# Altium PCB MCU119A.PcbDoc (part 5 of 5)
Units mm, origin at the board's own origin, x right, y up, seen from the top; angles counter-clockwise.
Board outline 58.62 x 144.37 mm, 6 copper layers (Top Signal, GND, Middle Signal, PWR, GND2, Bottom Signal), stack 1.566 mm thick; 316 components, 238 nets, 1210 pads, 1064 vias.
Unrouted connection lines stored in the file: 59.
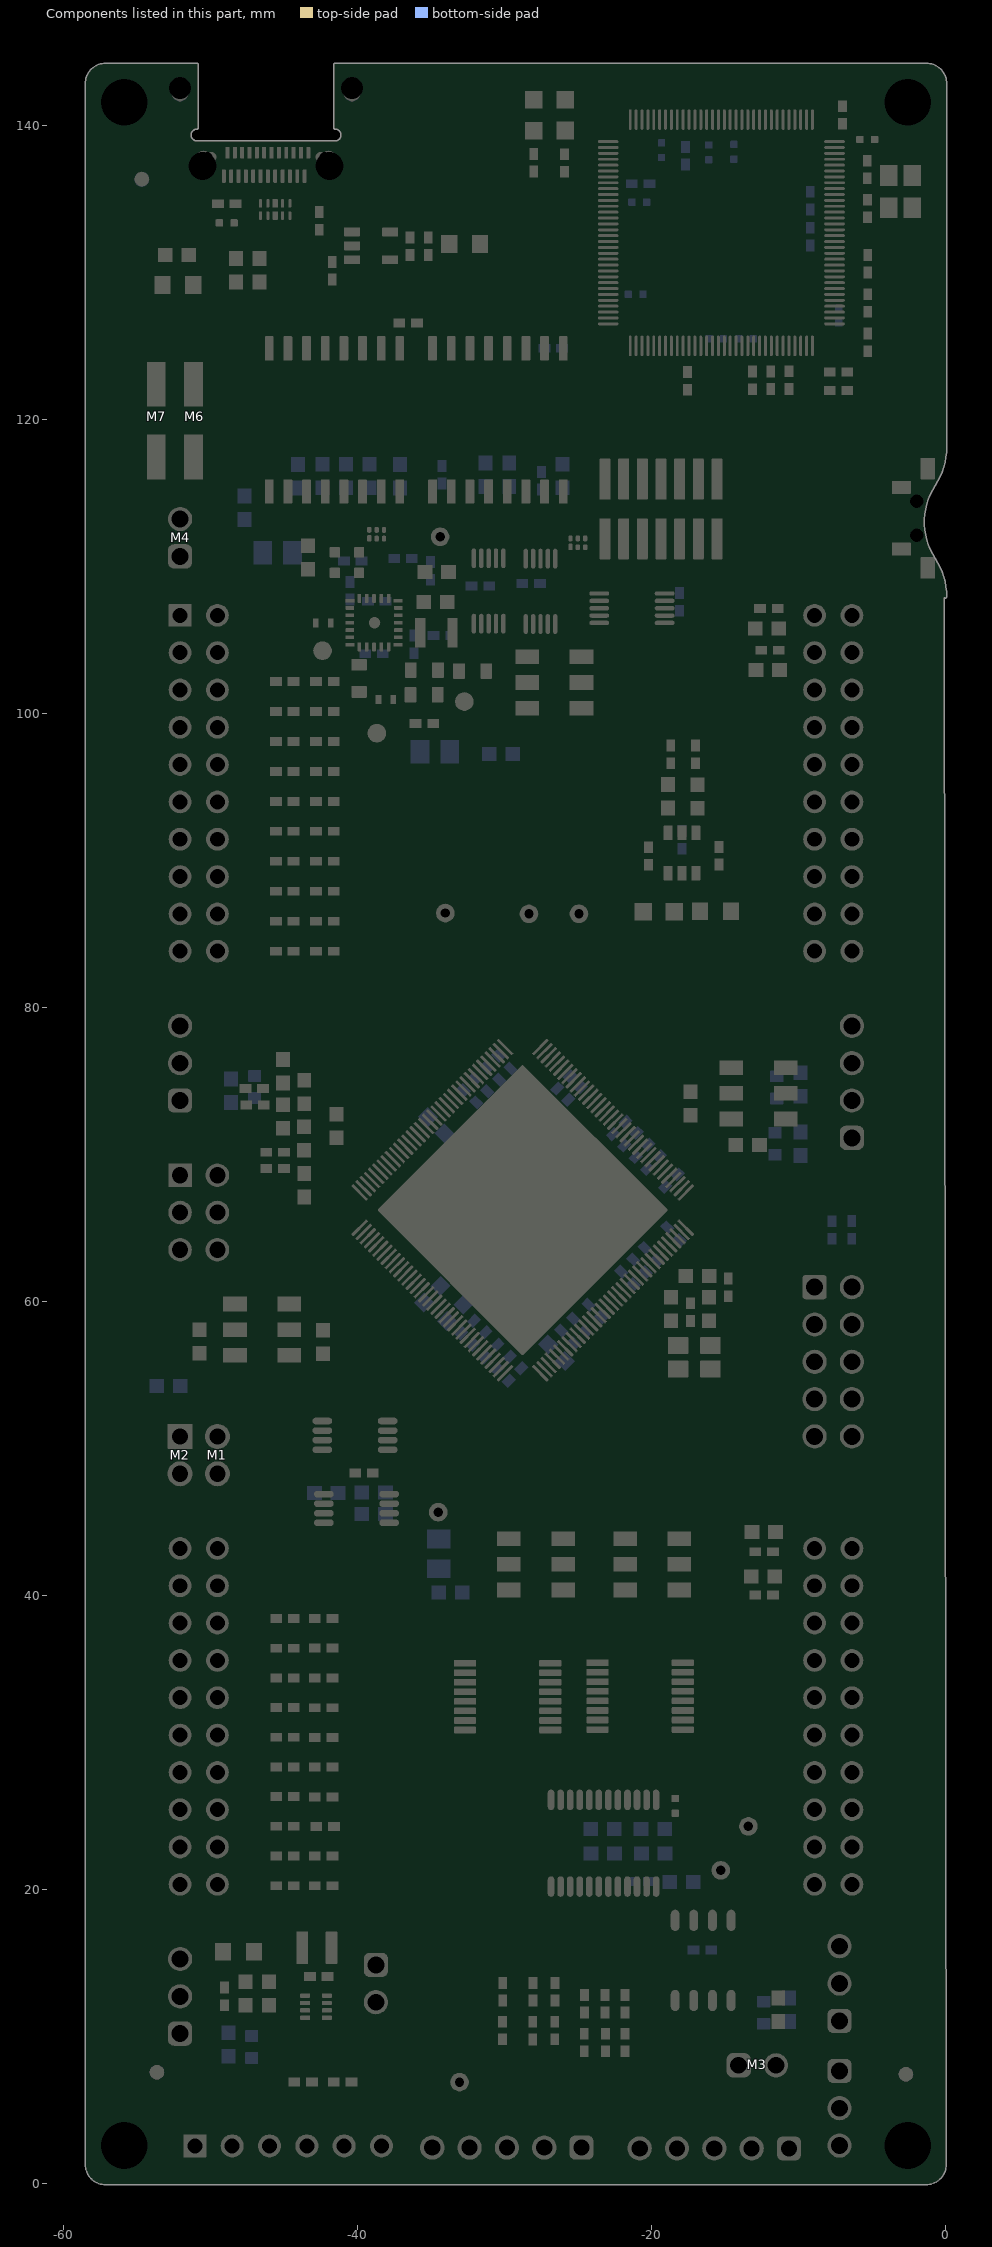
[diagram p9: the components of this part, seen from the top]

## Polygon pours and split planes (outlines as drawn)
+3V3_MCU on PWR "PWR_+3V3_MCU_P156" (solid, remove dead copper, pour order 156): -58.223,118.663 0.057,118.663 0.102,118.618 0.102,-0.1 -57.913,-0.1 -58.42,0.406 -58.42,118.466
VDDIO on PWR "PWR_VDDIO_P151" (solid, remove dead copper, pour order 151): -44.755,106.451 -43.043,106.451 -42.799,106.207 -42.799,102.982 -41.163,101.346 -38.383,101.346 -36.808,99.771 -29.267,99.771 -24.79,95.295 -24.79,83.134 -13.818,72.161 -13.818,58.369 -21.24,50.947 -32.811,50.947 -33.884,52.019 -33.884,55.168 -33.171,55.88 -32.741,55.88 -31.166,54.305 -30.638,54.305 -30.435,54.508 -27.021,54.508 -23.868,57.661 -22.819,57.661 -22.327,58.153 -22.327,59.381 -20.828,60.879 -19.683,60.879 -17.729,62.833 -17.729,67.31 -16.942,68.097 -16.942,68.97 -17.543,69.571 -18.376,69.571 -20.356,71.55 -20.356,72.803 -25.134,77.581 -29.139,77.581 -29.389,77.332 -32.194,77.332 -33.239,76.287 -33.376,76.287 -33.503,76.414 -33.503,78.202 -31.364,80.341 -31.364,91.985 -34.539,95.159 -42.785,95.159 -45.277,97.652 -45.277,105.929
VDD on PWR "PWR_VDD_P152" (solid, remove dead copper, pour order 152): -10.973,72.695 -8.534,72.695 -8.128,72.288 -8.128,68.442 -10.744,65.826 -10.744,53.721 -16.662,47.803 -36.394,47.803 -38.152,49.562 -38.152,56.463 -34.816,59.799 -32.561,57.543 -32.561,56.961 -34.138,55.384 -34.138,51.623 -33.289,50.775 -21.071,50.775 -13.584,58.261 -13.584,70.189 -11.125,72.649
VDDA on PWR "PWR_VDDA_P155" (solid, remove dead copper, pour order 155): -35.907,73.539 -35.708,73.339 -35.708,59.201 -38.456,56.453 -38.456,49.22 -36.734,47.498 -33.654,47.498 -33.306,47.15 -33.306,44.913 -33.795,44.425 -40.066,44.425 -43.84,48.199 -43.84,69.052 -39.354,73.539
+5V0_MCU on PWR "PWR_+5V0_MCU_P149" (solid, remove dead copper, pour order 149): -18.872,21.768 -17.602,20.498 -17.602,18.771 -17.602,1.549 -18.186,0.965 -50.952,0.965 -57.252,7.264 -57.252,117.128 -56.574,117.805 -46.844,117.805 -37.878,108.839 -33.731,108.839 -33.122,108.229 -33.122,101.189 -34.26,100.051 -36.982,100.051 -38.862,101.93 -41.275,101.93 -42.545,103.2 -42.545,106.704 -42.699,106.858 -46.634,106.858 -48.031,105.461 -49.479,105.461 -50.673,106.655 -50.673,107.351 -51.463,108.14 -52.819,108.14 -53.391,107.569 -53.391,75.336 -53.035,74.981 -47.9,74.981 -46.711,73.791 -46.711,70.917 -47.579,70.049 -52.963,70.049 -53.516,69.496 -53.516,57.633 -49.909,54.026 -47.981,52.098 -47.981,28.981 -40.767,21.768 -26.878,21.768
VDD on PWR "PWR_VDD_P150" (solid, remove dead copper, pour order 150): -36.494,94.92 -34.733,94.92 -31.623,91.81 -31.623,80.42 -34.087,77.956 -34.087,76.708 -33.503,76.124 -33.172,76.124 -32.093,77.203 -24.955,77.203 -20.549,72.796 -20.549,71.505 -18.284,69.24 -17.653,69.24 -17.272,68.859 -17.272,68.016 -17.907,67.381 -17.907,62.835 -19.756,60.985 -20.955,60.985 -22.479,59.461 -22.479,58.217 -22.911,57.785 -23.951,57.785 -27.096,54.64 -30.501,54.64 -30.759,54.381 -31.09,54.381 -33.376,56.667 -33.96,56.667 -35.532,58.239 -35.532,62.832 -35.532,73.682 -38.202,76.352 -38.202,93.212
+3V3_XDS110 on PWR "PWR_+3V3_XDS110_P091" (solid, remove dead copper, pour order 91): -4.058,140.669 -1.363,137.974 -1.363,125.196 -1.363,123.197 -3.5,121.06 -43.713,121.06 -45.206,122.553 -45.206,126.708 -37.534,134.381 -28.047,134.381 -21.759,140.669
+5V0_USB on PWR "PWR_+5V0_USB_P096" (solid, remove dead copper, pour order 96): -57.344,122.278 -56.576,121.314 -46.03,121.314 -39.669,132.16 -31.012,132.16 -22.274,140.897 -7.535,140.897 -7.533,140.899 -6.027,140.899 -5.599,141.328 -5.599,143.114 -6.223,143.737 -24,143.737 -29.202,138.535 -44.543,138.535 -55.338,138.535 -57.344,136.529
GND on Top Signal "TOP_SIGNAL_GND_P147" (solid, remove dead copper, pour order 147): -58.223,118.663 0.057,118.663 0.102,118.618 0.102,-0.1 -57.913,-0.1 -58.42,0.406 -58.42,118.466
+3V3_ISO_JTAG on Top Signal "TOP_SIGNAL_+3V3_ISO_JTAG_P114" (solid, remove dead copper, pour order 114): -45.794,118.119 -45.25,118.663 -14.892,118.663 -13.826,117.597 -13.826,113.667 -14.885,112.607 -44.556,112.607 -45.808,113.86
+5V0_MCU on Top Signal "TOP_SIGNAL_+5V0_MCU_P144" (solid, remove dead copper, pour order 144): -55.575,118.663 -53.105,118.663 -52.948,118.505 -52.948,114.016 -51.73,112.798 -48.722,112.798 -47.498,111.574 -47.498,106.223 -48.108,105.613 -50.165,105.613 -50.876,106.324 -50.876,107.4 -51.248,107.772 -57.353,107.772 -57.48,107.899 -57.48,117.14 -55.952,118.669 -55.778,118.669
GND on Top Signal "TOP_SIGNAL_GND_P125" (solid, remove dead copper, pour order 125): -30.822,68.647 -29.662,70.229 -29.649,70.229 -29.457,70.42 -28.513,70.42 -28.513,69.603 -27.534,69.603 -27.534,68.748 -27.635,68.647
+3V3_XDS110 on Top Signal "Top Signal-+3V3_XDS110" (solid, remove dead copper, pour order 100): -23.659,135.528 -23.659,133.176 -23.648,132.748 -20.742,132.748 -20.286,133.204 -20.286,137.677 -22.113,137.677 -22.309,137.481 -22.309,136.726 -23.659,136.726
+5V0_USB on Top Signal "TOP_SIGNAL_+5V0_USB_P101" (solid, remove dead copper, pour order 101): -44.387,133.316 -44.187,133.516 -41.764,133.516 -41.764,134.05 -41.441,134.373 -39.467,134.373 -39.467,132.437 -39.548,132.356 -40.921,132.356 -41.114,132.163 -41.114,131.547 -40.939,131.372 -39.718,131.372 -39.467,131.122 -39.467,130.446 -39.822,130.092 -44.118,130.092 -44.514,130.487
+5V0_USB on Top Signal "TOP_SIGNAL_+5V0_USB_P112" (solid, remove dead copper, pour order 112): -57.941,126.115 -53.045,126.115 -53.045,121.06 -57.941,121.06
USB_GND on Top Signal "TOP_SIGNAL_USB_GND_P122" (solid, remove dead copper, pour order 122): -57.788,143.737 -0.346,143.737 -0.346,121.06 -57.788,121.06
GND on Bottom Signal "BOTTOM_SIGNAL_GND_P143" (solid, remove dead copper, pour order 143): -58.318,118.663 0.057,118.663 0.102,118.618 0.102,-0.1 -57.761,-0.1 -58.42,0.559 -58.42,118.466 -58.293,118.593
USB_GND on Bottom Signal "BOTTOM_SIGNAL_USB_GND_P108" (solid, remove dead copper, pour order 108): -57.773,144.149 -0.346,144.149 -0.346,121.908 -1.337,121.314 -57.131,121.314 -57.773,121.81
GND on GND "GND_GND_P140" (solid, remove dead copper, pour order 140): -58.318,118.663 0.057,118.663 0.102,118.618 0.102,-0.1 -58.42,-0.1 -58.42,118.466 -58.293,118.593
USB_GND on GND "GND_USB_GND_P083" (solid, remove dead copper, pour order 83): -57.788,143.737 -0.346,143.737 -0.346,121.06 -57.788,121.06
GND on GND2 "GND2_GND_P142" (solid, remove dead copper, pour order 142): -58.318,118.663 0.057,118.663 0.102,118.618 0.102,-0.1 -58.42,-0.1 -58.42,118.466 -58.293,118.593
USB_GND on GND2 "GND2_USB_GND_P085" (solid, remove dead copper, pour order 85): -57.877,143.421 -57.15,144.149 -0.346,144.149 -0.346,121.06 -57.877,121.06
GND on Middle Signal "MIDDLE_SIGNAL_GND_P141" (solid, remove dead copper, pour order 141): -58.318,118.663 0.057,118.663 0.102,118.618 0.102,-0.1 -58.42,-0.1 -58.42,118.466 -58.293,118.593

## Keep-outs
Keep-Out Layer:
  lines w0.2: -50.911,144.165 -57.141,144.165 ccw(c-57.141,142.895) -58.411,142.895 -58.411,1.27 ccw(c-57.141,1.27) -57.141,0 -1.27,0 ccw(c-1.27,1.27) 0,1.27 0,107.97 ; -41.511,144.165 -1.261,144.165 cw(c-1.261,142.895) 0.009,142.895 0.009,118.13 cw(c-4.605,118.13) -0.753,115.59 ccw(c3.099,113.05) -0.753,110.51 cw(c-4.605,107.97) 0.009,107.97
  text ".Layer_Name" at -46.609,-58.823 h1.52

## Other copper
Top Signal:
  region net +3V3_MCU: -35.798,110.114 -35.128,109.444 -35.128,109.169 -36.711,107.586 -37.451,107.586 -37.499,107.634 -37.499,109.113 -36.499,110.114
  region net +3V3_MCU: -39.218,15.646 -36.068,15.646 -32.563,19.152 -32.563,23.438 -32.379,23.622 -31.42,23.622 -31.267,23.47 -31.267,18.644 -35.763,14.148 -39.116,14.148 -39.268,14.3 -39.218,14.351 -39.218,15.545
  pour cut-out: -39.853,107.747 -37.705,107.747 -37.499,107.54 -37.499,105.018 -37.666,104.851 -40.171,104.851 -40.345,105.025 -40.345,107.369 -40.016,107.697
  region net +5V0_MCU: -36.754,103.429 -36.754,100.218 -36.587,100.051 -36.259,100.051 -35.992,100.318 -35.992,103.729 -36.316,104.053 -36.489,104.053 -36.637,103.905
  region net +1V25_MCU: -33.833,106.502 -33.107,106.502 -33.02,106.415 -33.02,104.465 -32.588,104.033 -32.588,101.617 -32.05,101.079 -30.823,101.079 -30.312,100.569 -30.312,99.998 -30.64,99.67 -32.436,99.67 -33.579,100.813 -33.579,103.81 -33.871,104.102 -33.871,106.464
  region net NetL5_1: -36.576,105.791 -36.268,106.099 -35.769,106.099 -35.72,106.05 -35.72,105.428 -35.865,105.283 -36.205,105.283 -36.558,105.637 -36.558,105.664
  region net +5V0_MCU: -36.932,105.283 -36.551,105.283 -36.246,104.978 -36.246,101.086 -36.316,101.016 -36.51,101.016 -36.637,101.143 -36.637,104.867 -36.927,105.156
  region net VREG: -38.862,103.937 -38.362,103.937 -38.362,100.83 -38.456,100.736 -38.786,100.736 -38.862,100.813 -38.862,103.937
  region net +3V3_PMIC: -52.451,111.506 -51.533,111.506 -50.423,110.396 -41.045,110.396 -40.66,110.011 -40.66,108.3 -40.226,107.867 -40.226,107.683 -40.323,107.586 -41.546,107.586 -43.053,109.093 -52.045,109.093 -52.857,109.906 -52.857,111.261 -52.603,111.515
  text ".Layer_Name" at -46.38,-58.747 h1.52
Middle Signal:
  text ".Layer_Name" at -46.304,-58.721 h1.52
PWR:
  region net +3V3_MCU: -50.724,114.046 -48.997,112.319 -48.997,109.144 -51.206,106.934 -51.206,106.045 -51.359,105.893 -52.781,105.893 -52.857,105.969 -52.857,107.62 -50.724,109.753 -50.724,111.785 -51.384,112.446 -52.451,112.446 -52.883,112.878 -52.883,113.716 -52.553,114.046
  text ".Layer_Name" at -46.482,-58.874 h1.52
GND:
  text ".Layer_Name" at -46.498,-58.67 h1.52
GND2:
  text ".Layer_Name" at -46.457,-58.823 h1.52
Bottom Signal:
  pour cut-out: -36.964,110.993 -36.818,110.993 -36.818,110.229 -36.881,110.166 -37.052,110.338 -37.121,110.338
  pour cut-out: -40.766,107.371 -41.072,107.371 -41.072,107.949 -40.995,108.026 -40.422,108.026
  region net VDDIO: -44.983,111.811 -43.713,111.811 -43.485,111.582 -43.485,105.283 -43.637,105.131 -44.602,105.131 -45.085,105.613 -45.085,111.709
  region net +3V3_MCU: -47.015,114.071 -46.558,114.529 -46.558,117.691 -46.368,117.881 -45.776,117.881 -45.649,117.754 -45.649,110.384 -45.822,110.211 -47.015,110.211 -47.066,110.261 -47.066,111.825 -47.662,112.42 -52.426,112.42 -52.832,112.827 -52.832,113.665 -52.426,114.071
  region net +3V3_MCU: -52.857,50.622 -52.857,54.483 -52.578,54.762 -47.955,54.762 -47.615,54.423 -47.615,53.4 -47.879,53.137 -50.8,53.137 -51.333,52.603 -51.333,50.495 -51.562,50.267 -52.578,50.267 -52.883,50.571
  region net VDDA: -35.103,46.914 -33.833,46.914 -33.579,46.66 -33.579,43.282 -33.757,43.104 -35.128,43.104 -35.281,43.256 -35.281,46.736
  region net +3V3_MCU: -33.757,42.52 -33.655,42.418 -33.655,38.786 -33.96,38.481 -34.976,38.481 -35.281,38.786 -35.281,42.418 -35.179,42.52
  region net VDD: -35.23,98.298 -35.077,98.146 -35.077,93.828 -35.357,93.548 -36.271,93.548 -36.551,93.828 -36.551,98.146 -36.398,98.298
  region net +1V25_MCU: -34.265,96.672 -34.265,98.044 -33.985,98.323 -32.501,98.323 -31.877,98.948 -31.877,100.876 -31.667,101.086 -30.627,101.086 -30.328,100.787 -30.328,97.003 -30.759,96.571 -34.139,96.571 -34.241,96.672
  text ".Layer_Name" at -46.38,-58.747 h1.52

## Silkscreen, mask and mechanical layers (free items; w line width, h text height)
Top Overlay:
  drawing of 12598 lines, arcs and shapes, not listed
  text "*" at -52.88,134.332 h0.64
  text "*" at -52.2,133.081 h0.64
  text "*" at -2.076,130.296 h0.64
  text "XRSn" at -6.432,117.386 h1.85
  text "GND" at -48.886,115.853 h1.3 r90
  text "+5V0" at -55.236,115.243 h1.14 r90
  text "+3V3" at -33.401,111.817 h1.3
  text "IO.0" at -13.355,110.02 h1.3
  text "XDS110 Out" at -22.739,109.328 h1.3
  text "IO.1" at -13.343,109.063 h1.3
  text "*" at -14.351,105.486 h0.64
  text "1" at -23.616,103.793 h1.3
  text "IO.61" at -4.703,103.79 h1.3
  text "1" at -29.947,103.683 h1.3
  text "A1" at -54.788,103.66 h1.3
  text "*" at -14.351,101.86 h0.64
  text "IO.84" at -4.703,101.367 h1.3
  text "IN14" at -48.18,101.275 h1.14
  text "IO.43" at -56.19,101.238 h1.3
  text "IO.2" at -12.342,101.239 h1.3
  text "SEL1" at -29.693,100.965 h1.3 r90
  text "SEL2" at -22.86,100.94 h1.3 r90
  text "*" at -40.948,100.863 h0.64
  text "0" at -23.647,99.822 h1.3
  text "0" at -30.15,99.771 h1.3
  text "*" at -40.919,98.818 h0.64
  text "IO.42" at -56.211,98.745 h1.3
  text "IO.3" at -12.328,98.699 h1.3
  text "IO.17" at -4.703,98.699 h1.3
  text "A3" at -48.031,98.689 h1.3
  text "*" at -41.013,96.796 h0.64
  text "SEL1:" at -35.959,96.759 h1.3
  text "IO42," at -31.455,96.759 h1.3
  text "IO70," at -26.873,96.759 h1.3
  text "IO.4" at -12.36,96.159 h1.3
  text "XRSn" at -4.703,96.159 h1.3
  text "D1" at -48.066,96.148 h1.3
  text "IO.78" at -56.15,96.107 h1.3
  text "SEL2" at -35.959,95.489 h1.3
  text "IO43" at -31.455,95.489 h1.3
  text "IO71" at -26.873,95.489 h1.3
  text "*" at -41.02,94.697 h0.64
  text ":" at -34.224,93.953 h1.3
  text "0" at -35.113,93.851 h1.3
  text "0" at -33.751,93.851 h1.3
  text "XDS" at -30.836,93.851 h1.3
  text "BP" at -25.926,93.851 h1.3
  text "E7" at -47.998,93.619 h1.3
  text "IO.5" at -12.333,93.619 h1.3
  text "IO.58" at -4.703,93.619 h1.3
  text "A2" at -54.828,93.611 h1.3
  text "*" at -40.986,92.735 h0.64
  text ":" at -34.202,92.365 h1.3
  text "0" at -35.091,92.264 h1.3
  text "1" at -33.567,92.264 h1.3
  text "XDS" at -30.836,92.264 h1.3
  text "NC" at -25.926,92.264 h1.3
  text "IO.60" at -56.207,91.107 h1.3
  text "B4" at -48.004,91.107 h1.3
  text "IO.14" at -12.948,91.079 h1.3
  text "IO.59" at -4.703,91.079 h1.3
  text ":" at -34.196,90.79 h1.3
  text "1" at -34.958,90.689 h1.3
  text "0" at -33.723,90.689 h1.3
  text "BP" at -30.277,90.689 h1.3
  text "BP" at -25.926,90.689 h1.3
  text "*" at -40.986,90.656 h0.64
  text ":" at -34.187,89.23 h1.3
  text "1" at -34.949,89.129 h1.3
  text "1" at -33.552,89.129 h1.3
  text "BP" at -30.277,89.129 h1.3
  text "XDS" at -26.346,89.129 h1.3
  text "*" at -41.027,88.57 h0.64
  text "IO.72" at -56.204,88.539 h1.3
  text "A7" at -48.095,88.539 h1.3
  text "IO.15" at -12.92,88.538 h1.3
  text "IO.19" at -4.703,88.539 h1.3
  text "*" at -41.027,86.577 h0.64
  text "IO.57" at -56.211,85.999 h1.3
  text "C1" at -48.023,85.999 h1.3
  text "IO.64" at -12.948,85.999 h1.3
  text "IO.34" at -4.703,85.999 h1.3
  text "VDD" at -35.331,84.658 h1.3
  text "GND" at -25.375,84.633 h1.3
  text "VDDIO" at -30.023,84.607 h1.3
  text "*" at -41.008,84.531 h0.64
  text "IO.56" at -56.215,83.459 h1.3
  text "A0" at -48.047,83.459 h1.3
  text "IO.65" at -12.92,83.459 h1.3
  text "IO.18" at -4.703,83.46 h1.3
  text "*" at -40.986,82.359 h0.64
  text "BOOT" at -13.821,77.134 h1.3
  text "1" at -10.456,76.632 h1.3
  text "1" at -15.866,76.581 h1.3
  text "GPIO72" at -15.621,71.857 h1.3 r90
  text "GPIO84" at -8.839,71.857 h1.3 r90
  text "0" at -15.571,70.891 h1.3
  text "0" at -10.414,70.841 h1.3
  text "A4" at -55.387,68.016 h1.3
  text "B2" at -47.93,67.287 h1.3
  text "A5" at -55.399,65.386 h1.3
  text "B3" at -48.033,64.836 h1.3
  text "FSI" at -9.328,62.309 h1.3
  text "TXCLK" at -4.817,60.345 h1.3
  text "RXCLK" at -14.808,59.928 h1.3
  text "Ext Vref" at -53.67,59.741 h1.3
  text "TXD0" at -4.817,55.265 h1.3
  text "RXD0" at -13.868,55.016 h1.3
  text "Int Vref" at -53.594,54.712 h1.3
  text "VREFHI" at -42.647,52.807 h1.3
  text "LAUNCHXL-F29H85X" at -38.76,52.603 h1.27 r0.23
  text "RXD1" at -13.326,52.598 h1.3
  text "TXD1" at -4.817,52.598 h1.3
  text "+5V0 / TO / J7" at -47.828,47.65 h1.3
  text "+3V3 / TO / J5" at -57.471,47.62 h1.3
  text "GND" at -5.608,47.019 h1.3
  text "VDDA" at -35.941,46.482 h1.3
  text "IO.6" at -13.362,46.471 h1.3
  text "CAN" at -20.609,46.376 h1.3
  text "IO.7" at -13.369,45.543 h1.3
  text "ROUTE" at -21.31,45.258 h1.3
  text "*" at -14.342,45.259 h0.64
  text "BP" at -23.419,44.602 h1.3
  text "J12" at -24.994,43.485 h1.3
  text "J13" at -32.741,43.383 h1.3
  text "Q2" at -32.106,41.859 h1.3
  text "*" at -14.671,41.788 h0.64
  text "Q1" at -25.019,41.771 h1.3
  text "C2" at -54.779,40.279 h1.3
  text "IO.66" at -4.83,40.279 h1.3
  text "BP" at -24.867,40.056 h1.3
  text "BP" at -31.928,39.497 h1.3
  text "XCVR" at -23.622,38.176 h1.3
  text "QEP Select" at -30.928,38.129 h1.3
  text "IN15" at -48.209,37.813 h1.14
  text "IO.71" at -56.193,37.739 h1.3
  text "IO.11" at -4.83,37.739 h1.3
  text "IO.8" at -12.322,37.613 h1.3
  text "*" at -40.92,37.09 h0.64
  text "IO.70" at -56.086,35.22 h1.3
  text "IO.10" at -4.83,35.199 h1.3
  text "A6" at -48.022,35.19 h1.3
  text "*" at -40.92,35.099 h0.64
  text "IO.9" at -12.316,34.945 h1.3
  text "*" at -40.92,33.1 h0.64
  text "D5" at -48.047,32.657 h1.3
  text "IO.12" at -12.903,32.659 h1.3
  text "XRSn" at -4.83,32.659 h1.3
  text "IO.38" at -56.047,32.56 h1.3
  text "*" at -40.92,31.02 h0.64
  text "C3" at -54.805,30.119 h1.3
  text "C8" at -48.047,30.12 h1.3
  text "IO.13" at -12.888,30.119 h1.3
  text "IO.63" at -4.83,30.119 h1.3
  text "*" at -40.92,28.995 h0.64
  text "IO.24" at -12.921,27.706 h1.3
  text "IO.26" at -56.244,27.578 h1.3
  text "B9" at -48.123,27.578 h1.3
  text "IO.25" at -4.83,27.579 h1.3
  text "*" at -40.919,26.949 h0.64
  text "CANTX" at -13.31,25.222 h1.3 r90
  text "IO.103" at -56.807,25.039 h1.3
  text "C0" at -48.047,25.039 h1.3
  text "IO.62" at -4.83,25.039 h1.3
  text "*" at -40.92,24.97 h0.64
  text "IO.68" at -12.91,24.913 h1.3
  text "*" at -40.92,22.944 h0.64
  text "IO.41" at -56.193,22.498 h1.3
  text "E1" at -48.047,22.497 h1.3
  text "IO.76" at -12.914,22.499 h1.3
  text "IO.32" at -4.83,22.499 h1.3
  text "CANRX" at -14.561,22.403 h1.3 r90
  text "*" at -40.92,20.918 h0.64
  text "IO.22" at -56.234,19.959 h1.3
  text "E0" at -48.047,19.959 h1.3
  text "IO.127" at -4.83,19.959 h1.3
  text "IO.77" at -12.91,19.832 h1.3
  text "*" at -40.919,18.948 h0.64
  text "+5V0" at -55.782,17.15 h1.3
  text "ENABLE" at -37.104,14.254 h1.3
  text "+5V0" at -35.824,13.285 h1.3
  text "BOOST" at -36.645,12.261 h1.3
  text "+5V0_MCU" at -36.362,7.954 h1.3
  text "HI" at -4.728,7.061 h1.3 r90
  text "CAN" at -9.246,4.953 h1.3 r90
  text "LO" at -4.804,4.572 h1.3 r90
  text "EQEP2" at -30.886,4.47 h1.3
  text "EQEP1" at -16.942,4.394 h1.3
  text "SENT" at -45.466,4.216 h1.3
  text "GND" at -4.792,1.829 h1.3 r90
  text "5V" at -38.183,0.373 h1.3
  text "SENT3" at -49.962,0.356 h1.3
  text "GND" at -46.558,0.356 h1.3
  text "SENT6" at -41.707,0.356 h1.3
  text "5V" at -51.678,0.343 h1.3
  text "GND" at -44.12,0.33 h1.3
  text "GND" at -35.992,0.277 h1.3
  text "5V" at -32.995,0.277 h1.3
  text "GND" at -21.766,0.277 h1.3
  text "5V" at -18.845,0.277 h1.3
  text "2I" at -30.404,0.26 h1.3
  text "2B" at -27.915,0.26 h1.3
  text "2A" at -25.4,0.26 h1.3
  text "1I" at -16.07,0.26 h1.3
  text "1B" at -13.638,0.26 h1.3
  text "1A" at -11.098,0.26 h1.3
  text ".Layer_Name" at -46.533,-58.823 h1.52
Bottom Overlay:
  drawing of 12861 lines, arcs and shapes, not listed
  text "LAUNCHXL-F29H85X / Development Kit" at 0.009,139.615 h2.54
  text "www.ti.com/launchpad" at 0.009,118.823 h2.54
  text "J3/J1" at -49.051,108.578 h1.7
  text "J2/J4" at -5.877,108.456 h1.7
  text "40" at -10.583,106.319 h1.3
  text "39" at -10.59,103.883 h1.3
  text "2" at -53.763,103.779 h1.3
  text "19" at -3.496,103.779 h1.3
  text "38" at -10.583,101.366 h1.3
  text "3" at -53.763,101.239 h1.3
  text "23" at -46.558,101.235 h1.3
  text "18" at -3.496,101.239 h1.3
  text "4" at -53.763,98.699 h1.3
  text "24" at -46.549,98.699 h1.3
  text "37" at -10.583,98.699 h1.3
  text "17" at -3.496,98.699 h1.3
  text "5" at -53.763,96.159 h1.3
  text "25" at -46.549,96.159 h1.3
  text "36" at -10.583,96.159 h1.3
  text "16" at -3.496,96.159 h1.3
  text "6" at -53.763,93.619 h1.3
  text "26" at -46.549,93.619 h1.3
  text "35" at -10.583,93.619 h1.3
  text "15" at -3.496,93.619 h1.3
  text "7" at -53.763,91.079 h1.3
  text "27" at -46.549,91.079 h1.3
  text "34" at -10.583,91.079 h1.3
  text "14" at -3.496,91.079 h1.3
  text "8" at -53.763,88.539 h1.3
  text "28" at -46.549,88.539 h1.3
  text "33" at -10.583,88.539 h1.3
  text "13" at -3.496,88.539 h1.3
  text "9" at -53.763,85.999 h1.3
  text "29" at -46.549,85.999 h1.3
  text "32" at -10.583,85.999 h1.3
  text "12" at -3.496,85.999 h1.3
  text "10" at -53.763,83.459 h1.3
  text "31" at -10.583,83.459 h1.3
  text "11" at -3.75,83.459 h1.3
  text "30" at -46.57,83.442 h1.3
  text "'.PRJ_Number'.PCB_Rev" at -22.25,79.293 h2.75
  text "J6/J8" at -5.774,45.077 h1.7
  text "J7/J5" at -49.001,45.054 h1.7
  text "80" at -10.583,42.946 h1.3
  text "42" at -53.763,40.279 h1.3
  text "79" at -10.583,40.279 h1.3
  text "59" at -3.369,40.268 h1.3
  text "43" at -53.763,37.739 h1.3
  text "63" at -46.549,37.739 h1.3
  text "78" at -10.583,37.739 h1.3
  text "58" at -3.369,37.728 h1.3
  text "44" at -53.763,35.199 h1.3
  text "64" at -46.549,35.199 h1.3
  text "77" at -10.583,35.199 h1.3
  text "57" at -3.369,35.188 h1.3
  text "45" at -53.763,32.659 h1.3
  text "65" at -46.549,32.659 h1.3
  text "76" at -10.583,32.659 h1.3
  text "56" at -3.369,32.648 h1.3
  text "46" at -53.763,30.119 h1.3
  text "66" at -46.549,30.119 h1.3
  text "75" at -10.583,30.119 h1.3
  text "55" at -3.369,30.108 h1.3
  text "47" at -53.763,27.579 h1.3
  text "67" at -46.549,27.579 h1.3
  text "74" at -10.583,27.579 h1.3
  text "54" at -3.369,27.568 h1.3
  text "48" at -53.763,25.039 h1.3
  text "68" at -46.549,25.039 h1.3
  text "73" at -10.583,25.039 h1.3
  text "53" at -3.369,25.028 h1.3
  text "49" at -53.763,22.499 h1.3
  text "69" at -46.549,22.499 h1.3
  text "72" at -10.583,22.499 h1.3
  text "52" at -3.369,22.488 h1.3
  text "50" at -53.763,19.959 h1.3
  text "70" at -46.549,19.959 h1.3
  text "71" at -10.583,19.959 h1.3
  text "51" at -3.623,19.959 h1.3
  text "5V" at -32.557,4.191 h1.3 r270
  text "5V" at -18.644,4.191 h1.3 r270
  text "1I" at -16.129,4.191 h1.3 r270
  text "1A" at -10.897,4.191 h1.3 r270
  text "1B" at -13.513,4.14 h1.3 r270
  text "GND" at -35.253,4.115 h1.3 r270
  text "2I" at -30.124,4.115 h1.3 r270
  text "5V" at -51.562,4.064 h1.3 r270
  text "SENT3" at -48.744,4.064 h1.3 r270
  text "GND" at -46.253,4.064 h1.3 r270
  text "GND" at -43.942,4.064 h1.3 r270
  text "SENT6" at -41.148,4.064 h1.3 r270
  text "5V" at -38.735,4.064 h1.3 r270
  text "GND" at -21.234,4.064 h1.3 r270
  text "2B" at -27.661,3.988 h1.3 r270
  text "2A" at -25.07,3.988 h1.3 r270
  text ".Layer_Name" at -46.609,-58.747 h1.52
Top Paste:
  text ".Layer_Name" at -46.457,-58.67 h1.52
Bottom Paste:
  text ".Layer_Name" at -46.685,-58.747 h1.52
Top Solder:
  text ".Layer_Name" at -46.761,-58.975 h1.52
Bottom Solder:
  text ".Layer_Name" at -46.838,-58.594 h1.52
Drill Guide:
  text ".Layer_Name" at -46.228,-58.708 h1.52
M1 Board Outline:
  lines w0.254: -58.42,1.23 -58.42,142.879 ; -50.92,144.149 -57.15,144.149 ; -41.52,144.149 -1.27,144.149 cw(c-1.27,142.879) 0,142.879 0,118.114 cw(c-4.614,118.114) -0.762,115.574 ccw(c3.09,113.034) -0.762,110.494 cw(c-4.614,107.954) 0,107.954 0,1.168 ; -1.506,144.149 0,144.149 0,142.686 ; 0,1.264 0,0 -1.27,0 ; 0,1.27 cw(c-1.27,1.27) -1.27,0 ; -58.42,142.879 cw(c-57.15,142.879) -57.15,144.149 ; -58.42,142.879 -58.42,144.149 -57.15,144.149 ; -57.15,0 cw(c-57.15,1.27) -58.42,1.27 -58.42,0 -57.15,0 ; -57.15,0 -1.27,0
  text ".Layer_Name" at -46.453,-58.729 h1.52
M2 Board Dimensions:
  text ".Layer_Name" at -46.301,-58.77 h1.52
M3 3D STEP Top:
  text ".Layer_Name" at -46.482,-58.632 h1.52
M4 3D STEP Bottom:
  text ".Layer_Name" at -46.452,-58.684 h1.52
M5 Assembly Top:
  circle w0.203: c-39.649,132.994 r0.107
  circle w0.203: c-15.57,115.104 r0.171
  circle w0.203: c-19.101,31.267 r0.29
  circle w0.203: c-28.143,31.267 r0.306
  circle w0.203: c-25.984,123.241 r0.203
  circle w0.203: c-37.135,123.266 r0.217
  circle w0.203: c-40.284,107.569 r0.13
  lines w0.254: -68.466,-60.465 99.174,-60.465 ; -68.466,-55.301 99.225,-55.301 ; -68.466,-50.136 -68.466,-65.63 33.261,-65.63 99.225,-65.63 99.225,-50.136 -68.453,-50.136 -68.453,-65.63 -28.435,-65.63 ; -5.855,-65.63 -5.855,-50.136 ; 26.327,-55.301 26.327,-50.136 ; 47.663,-55.301 47.663,-50.136 ; 63.462,-65.795 63.462,-60.643
  text "U8" at -22.047,106.594 h1.5
  text "U11" at -30.81,32.582 h1.5
  text "U14" at -21.717,32.557 h1.5
  text "U13" at -23.597,22.346 h1.5
  text "U15" at -16.975,15.265 h1.5
  text "COMPONENTS MARKED 'DNP' SHOULD NOT BE POPULATED." at -31.75,-44.929 h1.52
  text "ASSEMBLY VARIANT:" at -31.763,-47.863 h1.52
  text ".VariantName" at -5.448,-47.863 h1.52
  text "PCB VIEWED FROM TOP SIDE" at -66.853,-53.493 h1.52
  text "BOARD #:" at -3.95,-53.493 h1.52
  text ".PRJ_Number" at 9.906,-53.493 h1.52
  text "REV:" at 31.356,-53.493 h1.52
  text ".PCB_Rev" at 38.76,-53.493 h1.52
  text "SVN REV:" at 52.642,-53.493 h1.52
  text ".VersionControl_RevNumber" at 65.494,-53.493 h1.52
  text ".Layer_Name" at -46.317,-58.683 h1.52
  text "TID #:" at -3.95,-58.658 h1.52
  text ".TID" at 9.906,-58.658 h1.52
  text "PLOT NAME =" at -66.853,-63.873 h1.52
  text ".plot_File_Name" at -46.393,-63.873 h1.52
  text "GENERATED    :" at -3.899,-63.873 h1.52
  text ".Print_Date" at 18.186,-63.873 h1.52
  text ".Print_Time" at 36.703,-63.873 h1.52
  text "TEXAS INSTRUMENTS" at 68.821,-63.873 h1.52
M6 Assembly Bottom:
  lines w0.254: -68.453,-55.326 99.238,-55.326 ; -68.402,-60.491 99.238,-60.491 ; -32.69,-65.821 -32.69,-60.669 ; -16.891,-55.326 -16.891,-50.161 ; 4.445,-55.326 4.445,-50.161 ; 36.627,-65.655 36.627,-50.161 ; 59.207,-65.655 99.225,-65.655 99.225,-50.161 -68.453,-50.161 -68.453,-65.655 -2.489,-65.655 99.238,-65.655 99.238,-50.161
  text "COMPONENTS MARKED 'DNP' SHOULD NOT BE POPULATED." at 93.967,-44.929 h1.52
  text ".VariantName" at 67.45,-47.875 h1.52
  text "ASSEMBLY VARIANT:" at 93.84,-47.875 h1.52
  text ".VersionControl_RevNumber" at -34.722,-53.518 h1.52
  text "SVN REV:" at -21.869,-53.518 h1.52
  text ".PCB_Rev" at -7.988,-53.518 h1.52
  text "REV:" at -0.584,-53.518 h1.52
  text ".PRJ_Number" at 20.866,-53.518 h1.52
  text "BOARD #:" at 34.722,-53.518 h1.52
  text "PCB VIEWED FROM BOTTOM SIDE" at 97.625,-53.518 h1.52
  text ".Layer_Name" at -46.291,-58.696 h1.52
  text ".TID" at 20.866,-58.683 h1.52
  text "TID #:" at 34.722,-58.683 h1.52
  text "TEXAS INSTRUMENTS" at -38.049,-63.899 h1.52
  text ".Print_Time" at -5.931,-63.899 h1.52
  text ".Print_Date" at 12.586,-63.899 h1.52
  text "GENERATED    :" at 34.671,-63.899 h1.52
  text ".plot_File_Name" at 77.165,-63.899 h1.52
  text "PLOT NAME =" at 97.625,-63.899 h1.52
M7 LPKF Text Top:
  text ".Layer_Name" at -46.292,-58.589 h1.52
M8 LPKF Text Bottom:
  text ".Layer_Name" at -46.275,-58.722 h1.52
M9 Title Sheet:
  drawing of 57 lines, arcs and shapes, not listed
  text "1" at -42.27,167.199 h1.78
  text "2" at 21.12,167.199 h1.78
  text "3" at 84.349,167.199 h1.78
  text "4" at 148.019,167.199 h1.78
  text "5" at 211.493,167.199 h1.78
  text "6" at 275.12,167.199 h1.78
  text "A" at -71.641,138.167 h1.78
  text "A" at 304.279,138.167 h1.78
  text "B" at -71.641,77.715 h1.78
  text "B" at 304.279,77.715 h1.78
  text "C" at -71.641,17.39 h1.78
  text "C" at 304.279,17.39 h1.78
  text "PROJECT TITLE:" at 227.063,-29.88 h1.14
  text ".PRJ_Title" at 228.333,-33.266 h1.78
  text "DESIGNED FOR:" at 227.063,-37.525 h1.14
  text ".PRJ_Customer" at 228.333,-41.081 h1.78
  text "D" at -71.641,-42.808 h1.78
  text "D" at 304.279,-42.808 h1.78
  text "FILE NAME:" at 227.063,-45.145 h1.14
  text ".PCB_File_Name_No_Path" at 228.333,-48.193 h1.78
  text "Texas Instruments (TI) and/or its licensors do not warrant the accuracy or completeness of this specification" at 100.838,-52.304 h1.14
  text "ENGINEER:" at 227.063,-52.511 h1.14
  text "LAYOUT BY:" at 265.29,-52.511 h1.14
  text "or any information contained therein. TI and/or its licensors do not warrant that this design will meet" at 99.695,-55.165 h1.14
  text ".PRJ_Engineer" at 228.333,-56.448 h1.78
  text ".PCB_Layout" at 266.573,-56.448 h1.78
  text "the specifications, will be suitable for your application or fit for any particular purpose, or will operate in" at 99.695,-58.027 h1.14
  text ".Layer_Name" at -46.406,-58.734 h1.52
  text "ALTIUM DESIGNER VERSION:" at 265.29,-60.385 h1.14
  text "an implementation. TI and/or its licensors do not warrant that the design is production worthy. You should" at 99.695,-60.889 h1.14
  text "completely validate and test your design implementation to confirm the system functionality for your application." at 100.838,-63.75 h1.14
  text ".print_Scale" at 228.333,-63.771 h1.78
  text ".Application_BuildNumber" at 266.573,-63.771 h1.78
  text "1" at -42.27,-69.021 h1.78
  text "2" at 21.12,-69.021 h1.78
  text "3" at 84.349,-69.021 h1.78
  text "4" at 148.019,-69.021 h1.78
  text "5" at 211.493,-69.021 h1.78
  text "6" at 275.12,-69.021 h1.78
M10 Fab Notes:
  drawing of 189 lines, arcs and shapes, not listed
  text "DESIGN INFORMATION" at 253.492,124.697 h1.52
  text "MIN. TRACK WIDTH:" at 237.121,121.341 h1.52
  text "5" at 264.965,121.341 h1.52
  text "MIL" at 268.896,121.341 h1.52
  text "0.15" at 262.407,118.393 h1.52
  text "MIN. CLEARANCE:" at 237.121,118.188 h1.52
  text "mm" at 268.896,118.188 h1.52
  text "MIN. VIA PAD SIZE:" at 237.121,115.035 h1.52
  text "0.45" at 262.407,115.035 h1.52
  text "mm" at 268.896,115.035 h1.52
  text "0.05mm (2MIL)" at 254.774,111.736 h1.52
  text "MINIMUM ANNULAR RING" at 228.758,111.527 h1.52
  text "EXTERNAL" at 272.757,111.527 h1.52
  text "PER" at 233.838,108.73 h1.52
  text "IPC-D-275 CLASS 2 LEVEL C" at 239.426,108.729 h1.52
  text "MIL, HOLES" at 277.227,106.177 h1.52
  text "+/-" at 267.259,105.959 h1.52
  text "+/-" at 288.95,105.959 h1.52
  text "REGISTRATION TOLERANCES:" at 228.758,105.932 h1.52
  text "METAL" at 259.232,105.932 h1.52
  text "5" at 273.868,105.932 h1.52
  text "3" at 295.026,105.932 h1.52
  text "MIL" at 297.979,105.932 h1.52
  text "HOLE SIZE TOLERANCE (UNLESS OTHERWISE SPECIFIED):" at 228.758,103.435 h1.52
  text "+/-" at 288.95,103.362 h1.52
  text "5" at 295.026,103.335 h1.52
  text "MIL" at 297.979,103.335 h1.52
  text "MATERIAL:" at 226.859,99.839 h1.52
  text "FR-4 High Tg" at 251.915,96.574 h1.52
  text "X" at 248.246,96.371 h1.52
  text "FR-408" at 237.553,96.257 h1.52
  text "OTHER" at 275.348,96.257 h1.52
  text "62 MIL (1.6mm) +/-10%" at 245.683,92.624 h1.52
  text "X" at 242.633,92.561 h1.52
  text "THICKNESS:" at 228.758,92.415 h1.52
  text "OTHER" at 278.32,92.415 h1.52
  text "TOLERANCE:" at 228.758,88.902 h1.52
  text "ANSI IPC-6012 TYPE 3 CLASS 2" at 254.825,88.902 h1.52
  text "IPC-A600" at 272.237,85.678 h1.85
  text "OTHER +/-" at 254.824,85.239 h1.52
  text "X" at 250.52,85.17 h1.52
  text "BOW & TWIST:" at 228.758,81.551 h1.52
  text "ANSI IPC-6012 TYPE 3 CLASS 2" at 254.825,81.551 h1.52
  text "X" at 250.266,78.439 h1.52
  text "IPC-A600" at 272.237,77.931 h1.85
  text "OTHER +/-" at 254.824,77.825 h1.52
  text "DRILLING:" at 226.859,74.508 h1.52
  text "NC_DRILL FILES" at 271.588,71.836 h1.52
  text "REFERENCE:" at 228.758,71.736 h1.52
  text "X" at 245.452,71.733 h1.52
  text "AS SHOWN" at 249.973,71.736 h1.52
  text "X" at 268.337,71.736 h1.52
  text "OTHER" at 279.158,68.123 h1.52
  text "PTH COPPER THICKNESS:" at 228.75,68.033 h1.52
  text "X" at 257.687,68.033 h1.52
  text "20-30 um" at 260.938,68.033 h1.52
  text "BOARD FINISH:" at 226.859,64.284 h1.52
  text "SILKSCREEN:" at 230.802,61.487 h1.52
  text "X" at 255.129,61.487 h1.52
  text "TOP" at 258.101,61.487 h1.52
  text "X" at 268.083,61.487 h1.52
  text "BOTTOM" at 271.08,61.487 h1.52
  text "SILKSCREEN COLOR:" at 230.802,57.545 h1.52
  text "X" at 255.104,57.545 h1.52
  text "WHITE" at 258.101,57.545 h1.52
  text "OTHER" at 271.08,57.545 h1.52
  text "RED" at 287.274,54.156 h2.03
  text "GREEN" at 261.428,53.901 h1.52
  text "OTHER" at 277.126,53.901 h1.52
  text "X" at 273.406,53.801 h1.52
  text "SOLDER RESIST COLOR:" at 230.802,53.727 h1.52
  text "MATTE" at 261.428,49.983 h1.52
  text "SEMI-GLOSS" at 277.114,49.967 h1.52
  text "IMMERSION GOLD (ENIG)" at 253.808,45.595 h1.52
  text "ENEPIG" at 287.782,45.412 h1.52
  text "SURFACE FINISH:" at 226.859,45.386 h1.52
  text "IMM. TIN/SILVER OR EQUIV" at 235.229,41.898 h1.52
  text "X" at 231.47,41.863 h1.52
  text "OTHER" at 271.588,41.798 h1.52
  text "ARRAY/PANEL:" at 226.859,37.852 h1.52
  text "CUT AND TRIM PER M1 BOARD OUTLINE" at 253.809,37.643 h1.52
  text "X" at 249.276,37.596 h1.52
  text "N.C. ROUTE" at 253.808,34.189 h1.52
  text "V. SCORE" at 275.805,34.189 h1.52
  text "CERTIFICATION:" at 226.859,30.91 h1.52
  text "MATERIALS AND WORKMANSHIP FOR ALL PCBS" at 245.274,30.91 h1.52
  text "TO MEET OR EXCEED THE REQUIREMENTS OF:" at 245.274,28.52 h1.52
  text "X" at 281.203,25.312 h1.52
  text "X" at 236.067,25.253 h1.52
  text "ANSI IPC-A-600F CLASS ->" at 239.318,25.253 h1.52
  text "2" at 283.971,25.253 h1.52
  text "1" at 275.97,25.215 h1.52
  text "3" at 292.963,25.215 h1.52
  text "X" at 256.692,21.502 h1.52
  text "RoHS" at 259.943,21.502 h1.52
  text "OTHER" at 276.31,21.502 h1.52
  text "PER ORDER" at 286.396,21.502 h1.52
  text "ALL BOARDS MUST MEET OR EXCEED UL94-V0 REQUIREMENTS." at 227.559,17.595 h1.52
  text "PCB MUST BEAR THE UL94V-0 UL REGISTERED MATERIAL ID NUMBER" at 227.559,14.647 h1.52
  text "ADDITIONAL REQUIREMENTS:" at 226.859,10.343 h1.52
  text "MICROSECTION:" at 228.758,7.622 h1.52
  text "YES" at 251.764,7.622 h1.52
  text "X" at 258.826,4.017 h1.52
  text "REQUIRED" at 273.646,3.956 h1.52
  text "BARE BOARD ELEC. TEST:" at 228.758,3.884 h1.52
  text "NONE" at 261.924,3.884 h1.52
  text "PER ORDER" at 288.683,3.884 h1.52
  text "XX MIL VIAS REQUIRE NON-CONDUCTIVE FILL AND PLANARIZE" at 233.029,-1.322 h1.5
  text "XX MIL VIAS REQUIRE CONDUCTIVE FILL AND PLANARIZE" at 233.232,-3.963 h1.52
  text "OUTER XX MIL VIAS REQUIRE 50 OHM SINGLE-ENDED IMPEDANCE" at 233.207,-8.113 h1.47
  text "LAYER 2 & 3 (INNER LAYERS) XX MIL WIDE, XX MIL SPACE / TRACES REQUIRE 100 OHM DIFFERENTIAL IMPEDANCE" at 233.004,-14.1 h1.52
  text ".Layer_Name" at -46.129,-58.705 h1.52
M12 Stackup:
  drawing of 399 lines, arcs and shapes, not listed
  text "Layer" at 89.629,121.924 h1.52
  text "Name" at 100.041,121.924 h1.52
  text "Material" at 123.656,121.924 h1.52
  text "Thickness" at 145.495,121.924 h1.52
  text "Constant" at 162,121.924 h1.52
  text "Board Layer Stack" at 176.475,121.924 h1.52
  text "Top Overlay" at 100.041,118.876 h1.52
  text "Top Solder" at 100.041,115.828 h1.52
  text "Solder Resist" at 123.656,115.828 h1.52
  text "0.40mil" at 145.495,115.828 h1.52
  text "3.5" at 162,115.828 h1.52
  text "1" at 89.629,112.78 h1.52
  text "Top Signal" at 100.041,112.78 h1.52
  text "1.40mil" at 145.495,112.78 h1.52
  text "Dielectric 1" at 100.041,109.732 h1.52
  text "FR-4" at 123.656,109.732 h1.52
  text "6.25mil" at 145.495,109.732 h1.52
  text "4.2" at 162,109.732 h1.52
  text "2" at 89.629,106.684 h1.52
  text "GND" at 100.041,106.684 h1.52
  text "1.40mil" at 145.495,106.684 h1.52
  text "Dielectric 2" at 100.041,103.636 h1.52
  text "FR-4" at 123.656,103.636 h1.52
  text "16.10mil" at 145.495,103.636 h1.52
  text "4.2" at 162,103.636 h1.52
  text "3" at 89.629,100.588 h1.52
  text "Middle Signal" at 100.041,100.588 h1.52
  text "1.40mil" at 145.495,100.588 h1.52
  text "Dielectric 3" at 100.041,97.54 h1.52
  text "FR-4" at 123.656,97.54 h1.52
  text "8.54mil" at 145.495,97.54 h1.52
  text "4.2" at 162,97.54 h1.52
  text "4" at 89.629,94.492 h1.52
  text "PWR" at 100.041,94.492 h1.52
  text "1.40mil" at 145.495,94.492 h1.52
  text "Dielectric 4" at 100.041,91.444 h1.52
  text "FR-4" at 123.656,91.444 h1.52
  text "16.10mil" at 145.495,91.444 h1.52
  text "4.2" at 162,91.444 h1.52
  text "5" at 89.629,88.396 h1.52
  text "GND2" at 100.041,88.396 h1.52
  text "1.40mil" at 145.495,88.396 h1.52
  text "Dielectric 5" at 100.041,85.348 h1.52
  text "FR-4" at 123.656,85.348 h1.52
  text "6.25mil" at 145.495,85.348 h1.52
  text "4.2" at 162,85.348 h1.52
  text "6" at 89.629,82.3 h1.52
  text "Bottom Signal" at 100.041,82.3 h1.52
  text "1.40mil" at 145.495,82.3 h1.52
  text "Bottom Solder" at 100.041,79.252 h1.52
  text "Solder Resist" at 123.656,79.252 h1.52
  text "0.40mil" at 145.495,79.252 h1.52
  text "3.5" at 162,79.252 h1.52
  text "Bottom Overlay" at 100.041,76.204 h1.52
  text ".Layer_Name" at -46.482,-58.785 h1.52
M13 Component Bodies Top:
  text ".Layer_Name" at -46.255,-58.663 h1.52
M14 Component Bodies Bottom:
  text ".Layer_Name" at -46.446,-58.512 h1.52
M15 Courtyards Top:
  text ".Layer_Name" at -46.223,-58.536 h1.52
M16 Courtyards Bottom:
  text ".Layer_Name" at -46.315,-58.568 h1.52
Drill Drawing:
  circle w0.254: c90.596,43.181 r0.548
  circle w0.254: c90.596,43.181 r0.914
  lines w0.254: 89.682,13.471 90.596,13.928 91.51,13.471 91.053,14.385 91.51,15.3 90.596,14.843 89.682,15.3 90.139,14.385 89.682,13.471 ; 89.682,19.413 91.51,19.413 90.596,17.585 89.682,19.413 ; 89.682,22.156 90.139,22.156 90.596,21.699 91.053,22.156 91.51,22.156 91.053,22.613 91.51,23.07 91.053,23.07 90.596,23.527 90.139,23.07 89.682,23.07 90.139,22.613 89.682,22.156 ; 89.682,26.269 90.139,26.269 90.596,25.812 91.053,26.269 91.51,26.269 91.053,26.726 91.51,27.183 91.053,27.183 90.596,27.64 90.139,27.183 89.682,27.183 90.139,26.726 89.682,26.269 ; 89.682,30.383 90.139,30.383 90.139,29.926 91.053,29.926 91.053,30.383 91.51,30.383 91.51,31.297 91.053,31.297 91.053,31.754 90.139,31.754 90.139,31.297 89.682,31.297 89.682,30.383 ; 89.682,35.868 91.51,35.868 90.596,34.039 89.682,35.868 ; 89.682,39.067 90.596,38.153 91.51,39.067 90.596,39.981 89.682,39.067 ; 89.682,46.38 91.51,46.38 91.51,48.208 89.682,48.208 89.682,46.38 ; 89.682,50.494 89.682,50.951 90.139,51.408 89.682,51.865 89.682,52.322 90.139,52.322 90.596,51.865 91.053,52.322 91.51,52.322 91.51,51.865 91.053,51.408 91.51,50.951 91.51,50.494 91.053,50.494 90.596,50.951 90.139,50.494 89.682,50.494 ; 89.682,58.721 90.596,59.178 91.51,58.721 91.053,59.635 91.51,60.549 90.596,60.092 89.682,60.549 90.139,59.635 89.682,58.721 ; 90.047,13.837 90.596,14.111 91.144,13.837 90.87,14.385 91.144,14.934 90.596,14.66 90.047,14.934 90.322,14.385 90.047,13.837 ; 90.047,19.048 91.144,19.048 90.596,17.951 90.047,19.048 ; 90.047,22.338 90.322,22.338 90.596,22.064 90.87,22.338 91.144,22.338 90.87,22.613 91.144,22.887 90.87,22.887 90.596,23.161 90.322,22.887 90.047,22.887 90.322,22.613 90.047,22.338 ; 90.047,30.566 90.322,30.566 90.322,30.291 90.87,30.291 90.87,30.566 91.144,30.566 91.144,31.114 90.87,31.114 90.87,31.388 90.322,31.388 90.322,31.114 90.047,31.114 90.047,30.566
  lines w0.305: 88.048,12.237 194.351,12.237 ; 88.048,61.6 194.351,61.6 ; 99.223,8.124 99.223,65.714 ; 110.118,8.124 110.118,65.714 ; 129.637,8.124 129.637,65.714 ; 138.208,8.124 138.208,65.714 ; 150.614,8.124 150.614,65.714 ; 175.619,8.124 175.619,65.714 ; 88.048,8.124 194.351,8.124 194.351,65.714 88.048,65.714 88.048,8.124
  text "Symbol" at 90.517,62.834 h2.38
  text "Count" at 100.457,62.834 h2.38
  text "Hole Size" at 111.352,62.834 h2.38
  text "Plated" at 130.871,62.834 h2.38
  text "Hole Type" at 139.442,62.834 h2.38
  text "Drill Layer Pair" at 151.848,62.834 h2.38
  text "Hole Tolerance" at 176.853,62.834 h2.38
  text "148" at 100.457,58.721 h1.98
  text "7.87mil (0.200mm)" at 111.352,58.721 h1.98
  text "PTH" at 130.871,58.721 h1.98
  text "Round" at 139.442,58.721 h1.98
  text "Top Signal - Bottom Signal" at 151.848,58.721 h1.98
  text "916" at 100.457,54.607 h1.98
  text "8.00mil (0.203mm)" at 111.352,54.607 h1.98
  text "PTH" at 130.871,54.607 h1.98
  text "Round" at 139.442,54.607 h1.98
  text "Top Signal - Bottom Signal" at 151.848,54.607 h1.98
  text "A" at 89.733,54.353 h1.83
  text "8" at 100.457,50.494 h1.98
  text "25.00mil (0.635mm)" at 111.352,50.494 h1.98
  text "PTH" at 130.871,50.494 h1.98
  text "Round" at 139.442,50.494 h1.98
  text "Top Signal - Bottom Signal" at 151.848,50.494 h1.98
  text "2" at 100.457,46.38 h1.98
  text "27.56mil (0.700mm)" at 111.352,46.38 h1.98
  text "PTH" at 130.871,46.38 h1.98
  text "Slot" at 139.442,46.38 h1.98
  text "Top Signal - Bottom Signal" at 151.848,46.38 h1.98
  text "2" at 100.457,42.266 h1.98
  text "35.43mil (0.900mm)" at 111.352,42.266 h1.98
  text "NPTH" at 130.871,42.266 h1.98
  text "Round" at 139.442,42.266 h1.98
  text "Top Signal - Bottom Signal" at 151.848,42.266 h1.98
  text "86" at 100.457,38.153 h1.98
  text "40.16mil (1.020mm)" at 111.352,38.153 h1.98
  text "PTH" at 130.871,38.153 h1.98
  text "Round" at 139.442,38.153 h1.98
  text "Top Signal - Bottom Signal" at 151.848,38.153 h1.98
  text "10" at 100.457,34.039 h1.98
  text "43.31mil (1.100mm)" at 111.352,34.039 h1.98
  text "PTH" at 130.871,34.039 h1.98
  text "Round" at 139.442,34.039 h1.98
  text "Top Signal - Bottom Signal" at 151.848,34.039 h1.98
  text "10" at 100.457,29.926 h1.98
  text "43.31mil (1.100mm)" at 111.352,29.926 h1.98
  text "PTH" at 130.871,29.926 h1.98
  text "Round" at 139.442,29.926 h1.98
  text "Top Signal - Bottom Signal" at 151.848,29.926 h1.98
  text "+/-1.97mil" at 176.853,29.926 h1.98
  text "32" at 100.457,25.812 h1.98
  text "45.28mil (1.150mm)" at 111.352,25.812 h1.98
  text "PTH" at 130.871,25.812 h1.98
  text "Round" at 139.442,25.812 h1.98
  text "Top Signal - Bottom Signal" at 151.848,25.812 h1.98
  text "2" at 100.457,21.699 h1.98
  text "59.06mil (1.500mm)" at 111.352,21.699 h1.98
  text "PTH" at 130.871,21.699 h1.98
  text "Slot" at 139.442,21.699 h1.98
  text "Top Signal - Bottom Signal" at 151.848,21.699 h1.98
  text "2" at 100.457,17.585 h1.98
  text "74.80mil (1.900mm)" at 111.352,17.585 h1.98
  text "PTH" at 130.871,17.585 h1.98
  text "Slot" at 139.442,17.585 h1.98
  text "Top Signal - Bottom Signal" at 151.848,17.585 h1.98
  text "4" at 100.457,13.471 h1.98
  text "125.00mil (3.175mm)" at 111.352,13.471 h1.98
  text "NPTH" at 130.871,13.471 h1.98
  text "Round" at 139.442,13.471 h1.98
  text "Top Signal - Bottom Signal" at 151.848,13.471 h1.98
  text "1222 Total" at 100.457,9.358 h1.98
  text "Slot definitions :" at 90.517,6.478 h1.98
  text "Routed Path Length" at 105.43,6.478 h1.98
  text "= Calculated from tool start centre position to tool end centre position." at 123.289,6.478 h1.98
  text "Hole Length" at 105.43,4.833 h1.98
  text "= Routed Path Length + Tool Size = Slot length as defined in the PCB layout" at 116.678,4.833 h1.98
  text ".Layer_Name" at -45.994,-58.589 h1.52
Mechanical 17:
  text ".Layer_Name" at -46.177,-58.69 h1.52
Mechanical 18:
  text ".Layer_Name" at -46.126,-58.759 h1.52
Mechanical 19:
  text ".Layer_Name" at -46.122,-58.568 h1.52

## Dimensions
-57.15,144.149 to -57.15,0 on M2 Board Dimensions
-58.217,-1.245 to 0.203,-1.245 on M2 Board Dimensions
